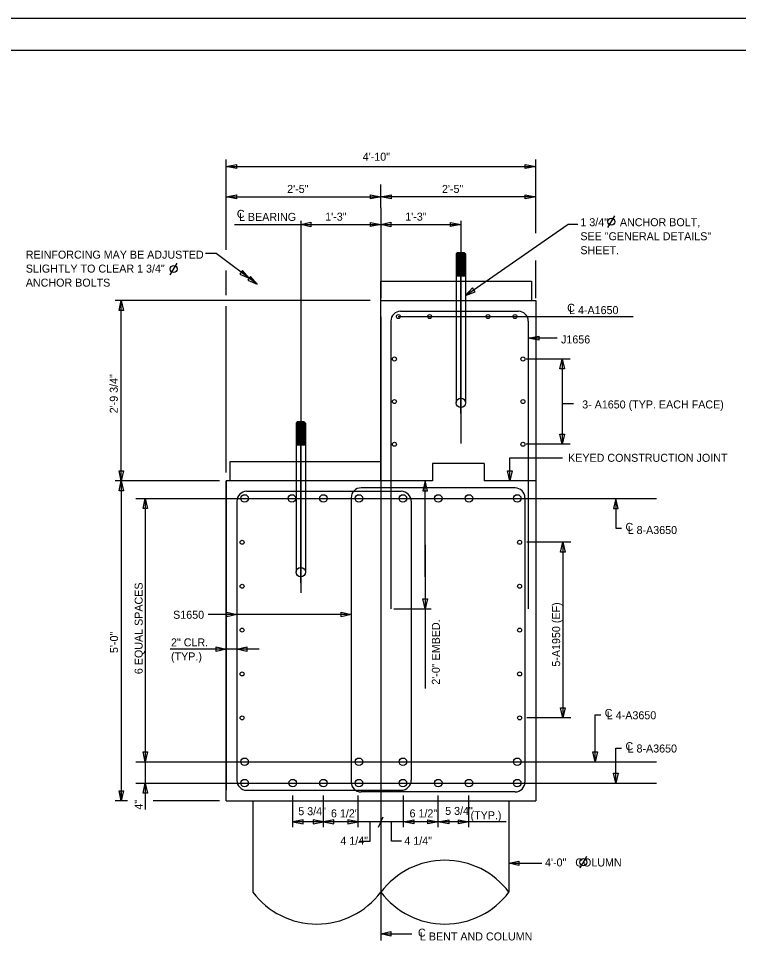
# Model space of a CAD drawing. Extents: x 1970675.2 to 1970711.3, y 796145.2 to 796167.2.
# Drawn here: x 1970689.32 to 1970700.57, y 796152.85 to 796167.25 of the extents above; entities that cross this region are included whole.
import ezdxf

# ---------------------------------------------------------------- set-up
doc = ezdxf.new("R2010")
doc.units = 0
for name, color, linetype in [('BR_AUTO DIMENSION', 7, 'Continuous'), ('BR_BORDER LINES', 7, 'Continuous'), ('BR_CENTER LINES', 7, 'Continuous'), ('BR_CONCRETE', 7, 'Continuous'), ('BR_REBAR', 7, 'Continuous'), ('BR_STRUCTURAL STEEL', 7, 'Continuous'), ('BR_TEXT', 7, 'Continuous'), ('Level 31', 7, 'Continuous')]:
    doc.layers.add(name, color=color, linetype=linetype)

msp = doc.modelspace()

# ---------------------------------------------------------------- linework, layer by layer
at = {"layer": 'BR_AUTO DIMENSION'}
for p, q in [((1970692.565, 796163.632), (1970692.565, 796165.043)), ((1970697.398, 796163.893), (1970697.398, 796165.043)), ((1970692.565, 796164.935), (1970697.398, 796164.935)), ((1970694.981, 796164.287), (1970694.981, 796164.655)), ((1970692.565, 796164.46), (1970694.981, 796164.46)), ((1970697.398, 796164.46), (1970694.981, 796164.46)), ((1970692.695, 796164.027), (1970693.731, 796164.027)), ((1970693.731, 796164.027), (1970694.981, 796164.027)), ((1970694.981, 796164.027), (1970696.231, 796164.027)), ((1970696.304, 796162.919), (1970697.905, 796164.035)), ((1970697.905, 796164.035), (1970698.058, 796164.035)), ((1970697.398, 796162.88), (1970697.398, 796163.469)), ((1970692.565, 796162.928), (1970692.565, 796163.311)), ((1970694.815, 796162.842), (1970690.832, 796162.842)), ((1970690.929, 796160.029), (1970690.929, 796162.842)), ((1970692.565, 796160.158), (1970692.565, 796162.752)), ((1970697.735, 796162.252), (1970697.282, 796162.252)), ((1970697.934, 796161.929), (1970697.252, 796161.929)), ((1970697.811, 796161.929), (1970697.811, 796160.598)), ((1970697.811, 796161.233), (1970697.989, 796161.233)), ((1970697.934, 796160.598), (1970697.252, 796160.598)), ((1970692.46, 796160.029), (1970690.832, 796160.029)), ((1970690.929, 796160.029), (1970690.929, 796155.029)), ((1970695.673, 796158.529), (1970695.673, 796160.029)), ((1970691.304, 796159.752), (1970691.304, 796154.893)), ((1970695.673, 796159.029), (1970695.673, 796156.786)), ((1970697.945, 796159.067), (1970697.262, 796159.067)), ((1970697.821, 796159.067), (1970697.821, 796156.326)), ((1970694.518, 796157.941), (1970692.285, 796157.941)), ((1970695.183, 796158.027), (1970695.766, 796158.027)), ((1970693.083, 796157.397), (1970691.69, 796157.397)), ((1970697.945, 796156.326), (1970697.262, 796156.326)), ((1970693.605, 796154.621), (1970693.605, 796155.115)), ((1970694.084, 796154.621), (1970694.084, 796155.115)), ((1970694.627, 796154.621), (1970694.627, 796155.115)), ((1970695.335, 796154.621), (1970695.335, 796155.115)), ((1970695.878, 796154.621), (1970695.878, 796155.115)), ((1970696.357, 796154.621), (1970696.357, 796155.115)), ((1970691.025, 796155.029), (1970690.832, 796155.029)), ((1970692.46, 796155.029), (1970691.427, 796155.029)), ((1970694.944, 796154.618), (1970695.019, 796154.783)), ((1970696.937, 796154.701), (1970693.622, 796154.701)), ((1970694.812, 796154.402), (1970694.812, 796154.701)), ((1970695.145, 796154.402), (1970695.145, 796154.701)), ((1970694.655, 796154.402), (1970694.812, 796154.402)), ((1970695.302, 796154.402), (1970695.145, 796154.402)), ((1970696.981, 796154.055), (1970697.493, 796154.055)), ((1970694.981, 796152.956), (1970695.464, 796152.956))]:
    msp.add_line(p, q, dxfattribs=at)
for points in [[(1970692.727, 796164.904), (1970692.565, 796164.935), (1970692.727, 796164.967)], [(1970697.235, 796164.967), (1970697.398, 796164.935), (1970697.235, 796164.904)], [(1970692.727, 796164.429), (1970692.565, 796164.46), (1970692.727, 796164.491)], [(1970694.819, 796164.491), (1970694.981, 796164.46), (1970694.819, 796164.429)], [(1970695.144, 796164.429), (1970694.981, 796164.46), (1970695.144, 796164.491)], [(1970697.235, 796164.491), (1970697.398, 796164.46), (1970697.235, 796164.429)], [(1970693.887, 796163.991), (1970693.731, 796164.027), (1970693.887, 796164.063)], [(1970694.819, 796164.058), (1970694.981, 796164.027), (1970694.819, 796163.996)], [(1970695.137, 796163.991), (1970694.981, 796164.027), (1970695.137, 796164.063)], [(1970696.069, 796164.058), (1970696.231, 796164.027), (1970696.069, 796163.996)], [(1970692.777, 796163.253), (1970692.924, 796163.189), (1970692.82, 796163.311)], [(1970692.902, 796163.16), (1970693.049, 796163.095), (1970692.945, 796163.218)], [(1970696.411, 796163.038), (1970696.304, 796162.919), (1970696.453, 796162.979)], [(1970690.893, 796162.686), (1970690.929, 796162.842), (1970690.965, 796162.686)], [(1970697.445, 796162.221), (1970697.282, 796162.252), (1970697.445, 796162.284)], [(1970697.775, 796161.773), (1970697.811, 796161.929), (1970697.847, 796161.773)], [(1970697.847, 796160.754), (1970697.811, 796160.598), (1970697.775, 796160.754)], [(1970690.965, 796160.185), (1970690.929, 796160.029), (1970690.893, 796160.185)], [(1970697.031, 796160.185), (1970696.995, 796160.029), (1970696.959, 796160.185)], [(1970690.893, 796159.873), (1970690.929, 796160.029), (1970690.965, 796159.873)], [(1970695.709, 796159.873), (1970695.673, 796160.029), (1970695.637, 796159.873)], [(1970691.268, 796159.596), (1970691.304, 796159.752), (1970691.34, 796159.596)], [(1970698.687, 796159.596), (1970698.651, 796159.752), (1970698.615, 796159.596)], [(1970697.785, 796158.911), (1970697.821, 796159.067), (1970697.857, 796158.911)], [(1970695.709, 796158.183), (1970695.673, 796158.027), (1970695.637, 796158.183)], [(1970692.575, 796157.977), (1970692.731, 796157.941), (1970692.575, 796157.905)], [(1970694.362, 796157.977), (1970694.518, 796157.941), (1970694.362, 796157.905)], [(1970692.409, 796157.433), (1970692.565, 796157.397), (1970692.409, 796157.361)], [(1970692.887, 796157.361), (1970692.731, 796157.397), (1970692.887, 796157.433)], [(1970697.857, 796156.482), (1970697.821, 796156.326), (1970697.785, 796156.482)], [(1970691.34, 796155.796), (1970691.304, 796155.64), (1970691.268, 796155.796)], [(1970698.363, 796155.796), (1970698.327, 796155.64), (1970698.291, 796155.796)], [(1970698.687, 796155.463), (1970698.651, 796155.307), (1970698.615, 796155.463)], [(1970690.965, 796155.185), (1970690.929, 796155.029), (1970690.893, 796155.185)], [(1970691.268, 796155.151), (1970691.304, 796155.307), (1970691.34, 796155.151)], [(1970693.768, 796154.732), (1970693.605, 796154.701), (1970693.768, 796154.669)], [(1970693.922, 796154.669), (1970694.084, 796154.701), (1970693.922, 796154.732)], [(1970694.247, 796154.732), (1970694.084, 796154.701), (1970694.247, 796154.669)], [(1970694.465, 796154.669), (1970694.627, 796154.701), (1970694.465, 796154.732)], [(1970695.498, 796154.669), (1970695.335, 796154.701), (1970695.498, 796154.732)], [(1970695.716, 796154.732), (1970695.878, 796154.701), (1970695.716, 796154.669)], [(1970696.041, 796154.669), (1970695.878, 796154.701), (1970696.041, 796154.732)], [(1970696.195, 796154.732), (1970696.357, 796154.701), (1970696.195, 796154.669)], [(1970697.137, 796154.019), (1970696.981, 796154.055), (1970697.137, 796154.091)], [(1970695.137, 796152.92), (1970694.981, 796152.956), (1970695.137, 796152.992)]]:
    msp.add_lwpolyline(points, close=True, dxfattribs=at)
for points in [[(1970693.049, 796163.095), (1970692.408, 796163.574), (1970692.243, 796163.574)], [(1970696.995, 796160.029), (1970696.995, 796160.385), (1970697.816, 796160.385)], [(1970698.651, 796159.752), (1970698.651, 796159.289), (1970698.739, 796159.289)], [(1970698.327, 796155.64), (1970698.327, 796156.372), (1970698.415, 796156.372)], [(1970698.651, 796155.307), (1970698.651, 796155.853), (1970698.739, 796155.853)]]:
    msp.add_lwpolyline(points, dxfattribs=at)
at = {"layer": 'BR_BORDER LINES'}
msp.add_line((1970710.736, 796166.746), (1970677.07, 796166.746), dxfattribs=at)
at = {"layer": 'BR_CENTER LINES'}
for p, q in [((1970694.981, 796164.287), (1970694.981, 796162.88)), ((1970693.731, 796164.087), (1970693.731, 796158.28)), ((1970696.231, 796164.087), (1970696.231, 796160.609)), ((1970696.231, 796161.076), (1970696.231, 796163.376)), ((1970694.981, 796162.586), (1970694.981, 796152.849)), ((1970695.251, 796162.592), (1970698.921, 796162.592)), ((1970693.731, 796158.436), (1970693.731, 796160.735)), ((1970691.157, 796159.752), (1970699.284, 796159.752)), ((1970691.157, 796155.64), (1970699.284, 796155.64)), ((1970691.157, 796155.307), (1970699.284, 796155.307))]:
    msp.add_line(p, q, dxfattribs=at)
at = {"layer": 'BR_CONCRETE'}
for p, q in [((1970694.981, 796160.029), (1970694.981, 796163.143)), ((1970694.981, 796163.143), (1970697.335, 796163.143)), ((1970697.335, 796163.143), (1970697.335, 796162.842)), ((1970694.981, 796162.842), (1970697.398, 796162.842)), ((1970697.398, 796162.842), (1970697.398, 796160.029)), ((1970692.627, 796160.029), (1970692.627, 796160.331)), ((1970692.627, 796160.331), (1970694.981, 796160.331)), ((1970696.592, 796160.298), (1970695.787, 796160.298)), ((1970695.787, 796160.298), (1970695.787, 796160.029)), ((1970696.592, 796160.298), (1970696.592, 796160.029)), ((1970692.565, 796160.029), (1970692.565, 796155.196)), ((1970692.565, 796155.029), (1970692.565, 796160.029)), ((1970694.981, 796160.029), (1970692.565, 796160.029)), ((1970695.787, 796160.029), (1970694.981, 796160.029)), ((1970697.398, 796160.029), (1970696.592, 796160.029)), ((1970697.398, 796160.029), (1970697.398, 796155.029)), ((1970692.565, 796155.029), (1970697.398, 796155.029)), ((1970692.981, 796155.029), (1970692.981, 796153.605)), ((1970696.981, 796155.029), (1970696.981, 796153.605))]:
    msp.add_line(p, q, dxfattribs=at)
for centre, start, end in [((1970695.981, 796152.851), 37.0023, 142.9977), ((1970693.981, 796154.359), 217.0023, 322.9977), ((1970695.981, 796154.359), 217.0023, 322.9977)]:
    msp.add_arc(centre, 1.252, start, end, dxfattribs=at)
at = {"layer": 'BR_REBAR'}
for p, q in [((1970695.29, 796162.675), (1970697.128, 796162.675)), ((1970695.136, 796162.522), (1970695.136, 796158.029)), ((1970697.282, 796162.522), (1970697.282, 796158.029)), ((1970692.885, 796159.863), (1970695.299, 796159.863)), ((1970697.077, 796159.917), (1970694.674, 796159.917)), ((1970692.731, 796159.709), (1970692.731, 796155.35)), ((1970694.518, 796159.761), (1970694.518, 796155.325)), ((1970695.455, 796159.707), (1970695.455, 796155.352)), ((1970697.231, 796159.764), (1970697.231, 796155.323)), ((1970692.885, 796155.196), (1970695.299, 796155.196)), ((1970697.078, 796155.169), (1970694.674, 796155.169))]:
    msp.add_line(p, q, dxfattribs=at)
for centre, radius in [((1970695.255, 796162.592), 0.0313), ((1970695.743, 796162.592), 0.0313), ((1970696.653, 796162.592), 0.0313), ((1970697.075, 796162.592), 0.0313), ((1970695.193, 796161.929), 0.0313), ((1970697.2, 796161.929), 0.0313), ((1970695.193, 796161.265), 0.0313), ((1970697.2, 796161.265), 0.0313), ((1970695.193, 796160.598), 0.0313), ((1970697.2, 796160.598), 0.0313), ((1970692.853, 796159.752), 0.0588), ((1970693.592, 796159.752), 0.0588), ((1970694.085, 796159.752), 0.0588), ((1970694.638, 796159.752), 0.0588), ((1970695.325, 796159.752), 0.0588), ((1970695.877, 796159.752), 0.0588), ((1970696.357, 796159.752), 0.0588), ((1970697.11, 796159.752), 0.0588), ((1970692.815, 796159.067), 0.0313), ((1970697.148, 796159.067), 0.0313), ((1970692.815, 796158.381), 0.0313), ((1970697.148, 796158.381), 0.0313), ((1970692.815, 796157.696), 0.0313), ((1970697.148, 796157.696), 0.0313), ((1970692.815, 796157.011), 0.0313), ((1970697.148, 796157.011), 0.0313), ((1970692.815, 796156.326), 0.0313), ((1970697.148, 796156.326), 0.0313), ((1970692.853, 796155.64), 0.0588), ((1970694.638, 796155.64), 0.0588), ((1970695.325, 796155.64), 0.0588), ((1970697.11, 796155.64), 0.0588), ((1970692.853, 796155.307), 0.0588), ((1970693.605, 796155.307), 0.0588), ((1970694.085, 796155.307), 0.0588), ((1970694.638, 796155.307), 0.0588), ((1970695.325, 796155.307), 0.0588), ((1970695.877, 796155.307), 0.0588), ((1970696.357, 796155.307), 0.0588), ((1970697.11, 796155.307), 0.0588)]:
    msp.add_circle(centre, radius, dxfattribs=at)
for centre, start, end in [((1970695.292, 796162.519), 91.025, 178.975), ((1970697.126, 796162.519), 1.025, 88.975), ((1970692.888, 796159.707), 91.025, 178.975), ((1970694.674, 796159.761), 90, 180), ((1970695.299, 796159.707), 0, 90), ((1970697.075, 796159.761), 1.025, 88.975), ((1970692.888, 796155.352), 181.025, 268.975), ((1970695.299, 796155.352), 270, 0), ((1970694.674, 796155.325), 180, 270), ((1970697.075, 796155.325), 271.025, 358.975)]:
    msp.add_arc(centre, 0.156, start, end, dxfattribs=at)
at = {"layer": 'BR_STRUCTURAL STEEL'}
for p, q in [((1970696.177, 796163.587), (1970696.158, 796163.569)), ((1970696.304, 796163.569), (1970696.158, 796163.569)), ((1970696.158, 796163.569), (1970696.158, 796162.67)), ((1970696.304, 796163.551), (1970696.158, 796163.551)), ((1970696.286, 796163.587), (1970696.177, 796163.587)), ((1970696.304, 796163.569), (1970696.286, 796163.587)), ((1970696.304, 796163.569), (1970696.304, 796162.67)), ((1970696.304, 796163.532), (1970696.158, 796163.532)), ((1970696.304, 796163.514), (1970696.158, 796163.514)), ((1970696.304, 796163.496), (1970696.158, 796163.496)), ((1970696.304, 796163.478), (1970696.158, 796163.478)), ((1970696.304, 796163.459), (1970696.158, 796163.459)), ((1970696.304, 796163.441), (1970696.158, 796163.441)), ((1970696.304, 796163.423), (1970696.158, 796163.423)), ((1970696.304, 796163.405), (1970696.158, 796163.405)), ((1970696.304, 796163.386), (1970696.158, 796163.386)), ((1970696.304, 796163.368), (1970696.158, 796163.368)), ((1970696.304, 796163.35), (1970696.158, 796163.35)), ((1970696.304, 796163.332), (1970696.158, 796163.332)), ((1970696.304, 796163.314), (1970696.158, 796163.314)), ((1970696.304, 796163.295), (1970696.158, 796163.295)), ((1970696.304, 796163.277), (1970696.158, 796163.277)), ((1970696.304, 796163.259), (1970696.158, 796163.259)), ((1970696.304, 796163.241), (1970696.158, 796163.241)), ((1970696.304, 796163.222), (1970696.158, 796163.222)), ((1970696.158, 796162.67), (1970696.158, 796161.243)), ((1970696.304, 796162.67), (1970696.304, 796161.246)), ((1970693.677, 796160.946), (1970693.658, 796160.928)), ((1970693.786, 796160.946), (1970693.677, 796160.946)), ((1970693.804, 796160.928), (1970693.786, 796160.946)), ((1970693.804, 796160.928), (1970693.658, 796160.928)), ((1970693.658, 796160.928), (1970693.658, 796160.029)), ((1970693.804, 796160.91), (1970693.658, 796160.91)), ((1970693.804, 796160.892), (1970693.658, 796160.892)), ((1970693.804, 796160.873), (1970693.658, 796160.873)), ((1970693.804, 796160.855), (1970693.658, 796160.855)), ((1970693.804, 796160.837), (1970693.658, 796160.837)), ((1970693.804, 796160.819), (1970693.658, 796160.819)), ((1970693.804, 796160.801), (1970693.658, 796160.801)), ((1970693.804, 796160.928), (1970693.804, 796160.029)), ((1970693.804, 796160.782), (1970693.658, 796160.782)), ((1970693.804, 796160.764), (1970693.658, 796160.764)), ((1970693.804, 796160.746), (1970693.658, 796160.746)), ((1970693.804, 796160.728), (1970693.658, 796160.728)), ((1970693.804, 796160.709), (1970693.658, 796160.709)), ((1970693.804, 796160.691), (1970693.658, 796160.691)), ((1970693.804, 796160.673), (1970693.658, 796160.673)), ((1970693.804, 796160.655), (1970693.658, 796160.655)), ((1970693.804, 796160.636), (1970693.658, 796160.636)), ((1970693.804, 796160.618), (1970693.658, 796160.618)), ((1970693.804, 796160.6), (1970693.658, 796160.6)), ((1970693.804, 796160.582), (1970693.658, 796160.582)), ((1970693.658, 796160.029), (1970693.658, 796158.602)), ((1970693.804, 796160.029), (1970693.804, 796158.605))]:
    msp.add_line(p, q, dxfattribs=at)
for centre in [(1970696.231, 796161.243), (1970693.731, 796158.602)]:
    msp.add_circle(centre, 0.0729, dxfattribs=at)
at = {"layer": 'BR_TEXT'}
for p, q in [((1970698.527, 796163.982), (1970698.632, 796164.164)), ((1970691.694, 796163.243), (1970691.799, 796163.425)), ((1970690.929, 796155.029), (1970690.929, 796155.177)), ((1970698.091, 796153.982), (1970698.196, 796154.164))]:
    msp.add_line(p, q, dxfattribs=at)
for centre in [(1970698.579, 796164.073), (1970691.747, 796163.334), (1970698.143, 796154.073)]:
    msp.add_circle(centre, 0.055, dxfattribs=at)
at = {"layer": 'Level 31'}
msp.add_line((1970711.236, 796167.246), (1970675.236, 796167.246), dxfattribs=at)

# ---------------------------------------------------------------- texts
at = {"layer": 'BR_AUTO DIMENSION'}
for s, p in [('4\'-10"', (1970694.698, 796165.025)), ('2\'-5"', (1970693.518, 796164.522)), ('2\'-5"', (1970695.935, 796164.522))]:
    msp.add_text(s, height=0.125, dxfattribs=at).set_placement(p)
at = {"layer": 'BR_TEXT'}
for s, p in [('C', (1970692.733, 796164.132)), ('L BEARING', (1970692.766, 796164.085)), ('1\'-3"', (1970694.112, 796164.089)), ('1\'-3"', (1970695.362, 796164.089)), ('C', (1970697.89, 796162.666)), ('L 4-A1650', (1970697.919, 796162.63)), ('J1656', (1970697.794, 796162.172)), ('3- A1650 (TYP. EACH FACE)', (1970698.124, 796161.157)), ('KEYED CONSTRUCTION JOINT', (1970697.904, 796160.324)), ('S1650', (1970691.738, 796157.873)), ('2" CLR.', (1970691.705, 796157.442)), ('(TYP.)', (1970691.705, 796157.223)), ('6 1/2"', (1970694.202, 796154.772)), ('6 1/2"', (1970695.429, 796154.772)), ('4 1/4"', (1970694.349, 796154.344)), ('4 1/4"', (1970695.348, 796154.344))]:
    msp.add_text(s, height=0.125, dxfattribs=at).set_placement(p)
for s, rotation, p in [('1 3/4"    ANCHOR BOLT, ', 360, (1970698.096, 796164.002)), ('SEE "GENERAL DETAILS"', 360, (1970698.096, 796163.783)), ('SHEET.', 360, (1970698.096, 796163.565)), ('REINFORCING MAY BE ADJUSTED', 360, (1970689.438, 796163.496)), ('SLIGHTLY TO CLEAR 1 3/4"  ', 360, (1970689.438, 796163.278)), ('ANCHOR BOLTS', 360, (1970689.438, 796163.059)), ('2\'-9 3/4"', 90, (1970690.874, 796161.081)), ('C', 360, (1970698.8, 796159.245)), ('L 8-A3650', 360, (1970698.834, 796159.196)), ('6 EQUAL SPACES', 90, (1970691.262, 796157.009)), ('5-A1950 (EF)', 90, (1970697.78, 796157.126)), ('2\'-0" EMBED.', 90, (1970695.902, 796156.844)), ('5\'-0"', 90, (1970690.878, 796157.338)), ('C', 360, (1970698.476, 796156.34)), ('L 4-A3650', 360, (1970698.509, 796156.304)), ('C', 360, (1970698.8, 796155.821)), ('L 8-A3650', 360, (1970698.833, 796155.785)), ('4"', 90, (1970691.262, 796154.893)), ('5 3/4"', 360, (1970693.692, 796154.806)), ('5 3/4"', 360, (1970695.985, 796154.811)), ('(TYP.)', 360, (1970696.381, 796154.743)), ('4\'-0"   COLUMN', 360, (1970697.544, 796154.006)), ('C', 360, (1970695.56, 796152.91)), ('L BENT AND COLUMN', 360, (1970695.591, 796152.851))]:
    msp.add_text(s, height=0.125, rotation=rotation, dxfattribs=at).set_placement(p)

doc.saveas('drawing.dxf')
